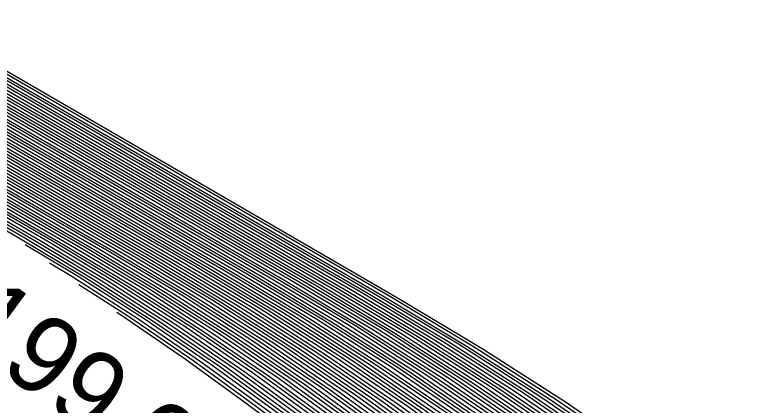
# Model space of a CAD drawing. Extents: x -500397 to -496810, y -1135552 to -1132176.
# Drawn here: x -500353.38 to -500334.38, y -1134763.08 to -1134753.02 of the extents above; entities that cross this region are included whole.
import ezdxf

# ---------------------------------------------------------------- set-up
doc = ezdxf.new("R2010")
doc.units = 0
doc.layers.add('30', color=7, linetype='Continuous')
doc.layers.add('40', color=7, linetype='Continuous')

msp = doc.modelspace()

# ---------------------------------------------------------------- linework, layer by layer
at = {"layer": '30'}
for points in [[(-500364.529, -1134750.173), (-500348.406, -1134759.531), (-500346.44, -1134760.711), (-500344.511, -1134761.947), (-500342.62, -1134763.239), (-500340.766, -1134764.589), (-500333.425, -1134770.097)], [(-500364.397, -1134750.167), (-500348.209, -1134759.562), (-500346.236, -1134760.747), (-500344.299, -1134761.988), (-500342.401, -1134763.286), (-500340.539, -1134764.64), (-500333.169, -1134770.171)], [(-500332.913, -1134770.245), (-500340.313, -1134764.692), (-500342.181, -1134763.332), (-500344.088, -1134762.029), (-500346.032, -1134760.783), (-500348.013, -1134759.594), (-500364.266, -1134750.161)], [(-500364.134, -1134750.155), (-500347.817, -1134759.625), (-500345.827, -1134760.82), (-500343.876, -1134762.071), (-500341.962, -1134763.379), (-500340.086, -1134764.744), (-500332.657, -1134770.319)], [(-500332.401, -1134770.393), (-500339.859, -1134764.796), (-500341.743, -1134763.425), (-500343.664, -1134762.112), (-500345.623, -1134760.856), (-500347.621, -1134759.657), (-500364.002, -1134750.15)], [(-500332.145, -1134770.467), (-500339.632, -1134764.848), (-500341.523, -1134763.472), (-500343.452, -1134762.153), (-500345.419, -1134760.892), (-500347.424, -1134759.689), (-500363.87, -1134750.144)], [(-500363.738, -1134750.138), (-500347.228, -1134759.72), (-500345.215, -1134760.929), (-500343.24, -1134762.195), (-500341.304, -1134763.518), (-500339.405, -1134764.9), (-500331.888, -1134770.541)], [(-500363.607, -1134750.132), (-500347.032, -1134759.752), (-500345.011, -1134760.965), (-500343.028, -1134762.236), (-500341.084, -1134763.565), (-500339.179, -1134764.952), (-500331.632, -1134770.615)], [(-500331.376, -1134770.689), (-500338.952, -1134765.004), (-500340.865, -1134763.611), (-500342.817, -1134762.277), (-500344.807, -1134761.001), (-500346.836, -1134759.784), (-500363.475, -1134750.126)], [(-500331.12, -1134770.763), (-500338.725, -1134765.055), (-500340.646, -1134763.658), (-500342.605, -1134762.319), (-500344.603, -1134761.038), (-500346.639, -1134759.815), (-500363.343, -1134750.121)], [(-500363.211, -1134750.115), (-500346.443, -1134759.847), (-500344.399, -1134761.074), (-500342.393, -1134762.36), (-500340.426, -1134763.704), (-500338.498, -1134765.107), (-500330.864, -1134770.836)], [(-500330.607, -1134770.91), (-500338.271, -1134765.159), (-500340.207, -1134763.751), (-500342.181, -1134762.401), (-500344.194, -1134761.11), (-500346.247, -1134759.879), (-500363.08, -1134750.109)], [(-500330.351, -1134770.984), (-500338.044, -1134765.211), (-500339.987, -1134763.797), (-500341.969, -1134762.443), (-500343.99, -1134761.147), (-500346.051, -1134759.91), (-500362.948, -1134750.103)], [(-500330.095, -1134771.058), (-500337.818, -1134765.263), (-500339.768, -1134763.844), (-500341.757, -1134762.484), (-500343.786, -1134761.183), (-500345.854, -1134759.942), (-500362.816, -1134750.097)], [(-500362.684, -1134750.092), (-500345.658, -1134759.974), (-500343.582, -1134761.22), (-500341.546, -1134762.525), (-500339.549, -1134763.89), (-500337.591, -1134765.315), (-500329.839, -1134771.132)], [(-500362.553, -1134750.086), (-500345.462, -1134760.005), (-500343.378, -1134761.256), (-500341.334, -1134762.566), (-500339.329, -1134763.937), (-500337.364, -1134765.367), (-500329.583, -1134771.206)], [(-500329.327, -1134771.28), (-500337.137, -1134765.419), (-500339.11, -1134763.983), (-500341.122, -1134762.608), (-500343.174, -1134761.292), (-500345.265, -1134760.037), (-500362.421, -1134750.08)], [(-500362.289, -1134750.074), (-500345.069, -1134760.068), (-500342.97, -1134761.329), (-500340.91, -1134762.649), (-500338.89, -1134764.03), (-500336.91, -1134765.47), (-500329.07, -1134771.354)], [(-500362.157, -1134750.068), (-500344.873, -1134760.1), (-500342.766, -1134761.365), (-500340.698, -1134762.69), (-500338.671, -1134764.076), (-500336.684, -1134765.522), (-500328.814, -1134771.428)], [(-500328.558, -1134771.502), (-500336.457, -1134765.574), (-500338.452, -1134764.123), (-500340.486, -1134762.732), (-500342.562, -1134761.401), (-500344.677, -1134760.132), (-500362.026, -1134750.063)], [(-500328.302, -1134771.576), (-500336.23, -1134765.626), (-500338.232, -1134764.169), (-500340.275, -1134762.773), (-500342.357, -1134761.438), (-500344.48, -1134760.163), (-500361.894, -1134750.057)], [(-500361.762, -1134750.051), (-500344.284, -1134760.195), (-500342.153, -1134761.474), (-500340.063, -1134762.814), (-500338.013, -1134764.216), (-500336.003, -1134765.678), (-500328.046, -1134771.649)], [(-500327.79, -1134771.723), (-500335.776, -1134765.73), (-500337.793, -1134764.262), (-500339.851, -1134762.856), (-500341.949, -1134761.51), (-500344.088, -1134760.227), (-500361.63, -1134750.045)], [(-500361.498, -1134750.04), (-500343.892, -1134760.258), (-500341.745, -1134761.547), (-500339.639, -1134762.897), (-500337.574, -1134764.308), (-500335.55, -1134765.782), (-500327.533, -1134771.797)], [(-500327.277, -1134771.871), (-500335.323, -1134765.834), (-500337.355, -1134764.355), (-500339.427, -1134762.938), (-500341.541, -1134761.583), (-500343.695, -1134760.29), (-500361.367, -1134750.034)], [(-500361.235, -1134750.028), (-500343.499, -1134760.322), (-500341.337, -1134761.62), (-500339.215, -1134762.98), (-500337.135, -1134764.401), (-500335.096, -1134765.885), (-500327.021, -1134771.945)], [(-500334.289, -1134771.301), (-500336.052, -1134770.098), (-500337.78, -1134768.841), (-500344.622, -1134763.707), (-500346.35, -1134762.449), (-500348.112, -1134761.245), (-500349.91, -1134760.092), (-500351.742, -1134758.993), (-500366.769, -1134750.271)], [(-500334.018, -1134771.386), (-500335.789, -1134770.177), (-500337.524, -1134768.915), (-500344.395, -1134763.759), (-500346.131, -1134762.496), (-500347.901, -1134761.286), (-500349.706, -1134760.129), (-500351.546, -1134759.024), (-500366.637, -1134750.265)], [(-500366.505, -1134750.26), (-500351.349, -1134759.056), (-500349.502, -1134760.165), (-500347.689, -1134761.327), (-500345.911, -1134762.542), (-500344.168, -1134763.81), (-500337.268, -1134768.989), (-500335.525, -1134770.256), (-500333.747, -1134771.47)], [(-500366.374, -1134750.254), (-500351.153, -1134759.088), (-500349.297, -1134760.201), (-500347.477, -1134761.369), (-500345.692, -1134762.589), (-500343.942, -1134763.862), (-500337.012, -1134769.063), (-500335.262, -1134770.336), (-500333.476, -1134771.555)], [(-500333.204, -1134771.639), (-500334.998, -1134770.415), (-500336.756, -1134769.137), (-500343.715, -1134763.914), (-500345.472, -1134762.635), (-500347.265, -1134761.41), (-500349.093, -1134760.238), (-500350.957, -1134759.119), (-500366.242, -1134750.248)], [(-500366.11, -1134750.242), (-500350.761, -1134759.151), (-500348.889, -1134760.274), (-500347.053, -1134761.451), (-500345.253, -1134762.682), (-500343.488, -1134763.966), (-500336.5, -1134769.21), (-500334.734, -1134770.494), (-500332.933, -1134771.723)], [(-500365.978, -1134750.236), (-500350.564, -1134759.183), (-500348.685, -1134760.311), (-500346.841, -1134761.492), (-500345.034, -1134762.728), (-500343.261, -1134764.018), (-500336.243, -1134769.284), (-500334.471, -1134770.574), (-500332.662, -1134771.808)], [(-500334.207, -1134770.653), (-500335.987, -1134769.358), (-500343.034, -1134764.07), (-500344.814, -1134762.775), (-500346.63, -1134761.534), (-500348.481, -1134760.347), (-500350.368, -1134759.214), (-500365.847, -1134750.231)], [(-500333.944, -1134770.732), (-500335.731, -1134769.432), (-500342.808, -1134764.122), (-500344.595, -1134762.821), (-500346.418, -1134761.575), (-500348.277, -1134760.383), (-500350.172, -1134759.246), (-500365.715, -1134750.225)], [(-500365.583, -1134750.219), (-500349.976, -1134759.277), (-500348.073, -1134760.42), (-500346.206, -1134761.616), (-500344.375, -1134762.868), (-500342.581, -1134764.174), (-500335.475, -1134769.506), (-500333.68, -1134770.811)], [(-500365.451, -1134750.213), (-500349.779, -1134759.309), (-500347.869, -1134760.456), (-500345.994, -1134761.658), (-500344.156, -1134762.914), (-500342.354, -1134764.225), (-500335.219, -1134769.58), (-500333.416, -1134770.891)], [(-500365.32, -1134750.207), (-500349.583, -1134759.341), (-500347.665, -1134760.492), (-500345.782, -1134761.699), (-500343.937, -1134762.961), (-500342.127, -1134764.277), (-500334.963, -1134769.654), (-500333.153, -1134770.97)], [(-500365.188, -1134750.202), (-500349.387, -1134759.372), (-500347.46, -1134760.529), (-500345.57, -1134761.74), (-500343.717, -1134763.007), (-500341.9, -1134764.329), (-500334.706, -1134769.728), (-500332.889, -1134771.049)], [(-500365.056, -1134750.196), (-500349.191, -1134759.404), (-500347.256, -1134760.565), (-500345.359, -1134761.782), (-500343.498, -1134763.054), (-500341.674, -1134764.381), (-500334.45, -1134769.802), (-500332.626, -1134771.129)], [(-500334.194, -1134769.876), (-500341.447, -1134764.433), (-500343.278, -1134763.1), (-500345.147, -1134761.823), (-500347.052, -1134760.601), (-500348.994, -1134759.436), (-500364.924, -1134750.19)], [(-500333.938, -1134769.95), (-500341.22, -1134764.485), (-500343.059, -1134763.147), (-500344.935, -1134761.864), (-500346.848, -1134760.638), (-500348.798, -1134759.467), (-500364.793, -1134750.184)], [(-500364.661, -1134750.178), (-500348.602, -1134759.499), (-500346.644, -1134760.674), (-500344.723, -1134761.906), (-500342.84, -1134763.193), (-500340.993, -1134764.537), (-500333.682, -1134770.023)], [(-500332.769, -1134772.362), (-500334.56, -1134771.217), (-500336.316, -1134770.018), (-500338.037, -1134768.767), (-500344.849, -1134763.655), (-500346.569, -1134762.403), (-500348.324, -1134761.203), (-500350.114, -1134760.056), (-500351.938, -1134758.961), (-500361.562, -1134753.376)], [(-500333.606, -1134772.093), (-500335.374, -1134770.963), (-500337.107, -1134769.781), (-500338.805, -1134768.545), (-500345.529, -1134763.499), (-500347.228, -1134762.263), (-500348.96, -1134761.079), (-500350.726, -1134759.947), (-500352.527, -1134758.866), (-500361.67, -1134753.56)], [(-500333.327, -1134772.183), (-500335.103, -1134771.048), (-500336.843, -1134769.86), (-500338.549, -1134768.619), (-500345.303, -1134763.551), (-500347.008, -1134762.31), (-500348.748, -1134761.121), (-500350.522, -1134759.983), (-500352.331, -1134758.898), (-500361.634, -1134753.498)], [(-500361.598, -1134753.437), (-500352.135, -1134758.929), (-500350.318, -1134760.02), (-500348.536, -1134761.162), (-500346.789, -1134762.356), (-500345.076, -1134763.603), (-500338.293, -1134768.693), (-500336.58, -1134769.939), (-500334.831, -1134771.132), (-500333.048, -1134772.272)], [(-500361.778, -1134753.744), (-500353.116, -1134758.771), (-500351.339, -1134759.838), (-500349.595, -1134760.955), (-500347.886, -1134762.124), (-500346.21, -1134763.344), (-500339.574, -1134768.324), (-500337.898, -1134769.543), (-500336.851, -1134770.257)], [(-500361.742, -1134753.683), (-500352.92, -1134758.803), (-500351.135, -1134759.874), (-500349.384, -1134760.997), (-500347.666, -1134762.17), (-500345.983, -1134763.395), (-500339.318, -1134768.397), (-500337.634, -1134769.622), (-500335.916, -1134770.794), (-500335.603, -1134770.995)], [(-500361.706, -1134753.621), (-500352.723, -1134758.834), (-500350.93, -1134759.911), (-500349.172, -1134761.038), (-500347.447, -1134762.217), (-500345.756, -1134763.447), (-500339.061, -1134768.471), (-500337.37, -1134769.701), (-500335.645, -1134770.879), (-500333.885, -1134772.004)], [(-500361.814, -1134753.805), (-500353.312, -1134758.74), (-500351.543, -1134759.801), (-500349.807, -1134760.914), (-500348.105, -1134762.078), (-500346.437, -1134763.292), (-500339.83, -1134768.25), (-500338.161, -1134769.463), (-500337.952, -1134769.606)], [(-500338.846, -1134769.078), (-500340.086, -1134768.176), (-500346.663, -1134763.24), (-500348.325, -1134762.031), (-500350.019, -1134760.873), (-500351.747, -1134759.765), (-500353.111, -1134758.946)], [(-500352.483, -1134759.41), (-500351.951, -1134759.729), (-500350.231, -1134760.832), (-500348.544, -1134761.985), (-500346.89, -1134763.188), (-500340.342, -1134768.102), (-500339.671, -1134768.59)], [(-500351.727, -1134759.967), (-500350.443, -1134760.79), (-500348.763, -1134761.938), (-500347.117, -1134763.136), (-500340.598, -1134768.028), (-500340.496, -1134768.103)], [(-500341.253, -1134767.655), (-500347.344, -1134763.084), (-500348.983, -1134761.892), (-500350.655, -1134760.749), (-500350.746, -1134760.69)]]:
    msp.add_lwpolyline(points, dxfattribs=at)

# ---------------------------------------------------------------- texts
at = {"layer": '40'}
for s, rotation, p in [('199,00', 323.595, (-500355.006, -1134761.276)), ('156,00', 327.72, (-500358.635, -1134763.516))]:
    msp.add_text(s, height=2, rotation=rotation, dxfattribs=at).set_placement(p)

doc.saveas('drawing.dxf')
